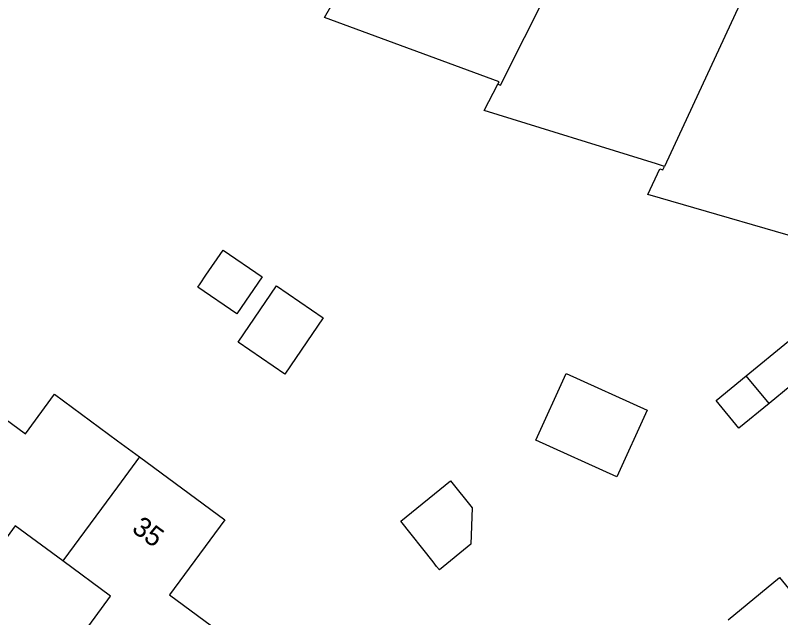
# Model space of a CAD drawing. Extents: x 163268 to 164360, y 381529 to 382285.
# Drawn here: x 163994.82 to 164033.56, y 382025.7 to 382056.18 of the extents above; entities that cross this region are included whole.
import ezdxf

# ---------------------------------------------------------------- set-up
doc = ezdxf.new("R2010")
doc.units = 0
doc.layers.add('IMGEO_Pand', color=7, linetype='Continuous')
doc.layers.add('IMGEO_Pand_nummerreeks', color=7, linetype='Continuous')

msp = doc.modelspace()

# ---------------------------------------------------------------- linework, layer by layer
at = {"layer": 'IMGEO_Pand'}
for points in [[(164019.237, 382052.689), (164019.38, 382052.637), (164024.227, 382062.276)], [(164032.042, 382058.22), (164033.103, 382060.347), (164033.389, 382060.206), (164033.142, 382059.704), (164036.288, 382058.228), (164035.748, 382057.131), (164037.56, 382056.281), (164037.279, 382055.681), (164040.358, 382054.205), (164037.138, 382047.488), (164037.634, 382047.251), (164036.26, 382044.384), (164026.833, 382047.109), (164027.447, 382048.409), (164027.599, 382048.361), (164027.68, 382048.535)], [(164032.042, 382058.22), (164032.141, 382058.171), (164027.68, 382048.535)], [(164019.237, 382052.689), (164019.304, 382052.818), (164010.469, 382056.066), (164011.179, 382057.32), (164011.327, 382057.26), (164011.412, 382057.412)], [(164027.68, 382048.535), (164027.274, 382048.661), (164018.547, 382051.364), (164019.237, 382052.689)], [(164004.471, 382043.025), (164005.337, 382044.296), (164007.31, 382042.951), (164006.036, 382041.081), (164004.063, 382042.426), (164004.177, 382042.593), (164004.471, 382043.025)], [(164008.035, 382042.486), (164010.408, 382040.869), (164008.468, 382038.023), (164006.095, 382039.641), (164008.035, 382042.486)], [(164031.818, 382037.945), (164033.955, 382039.693), (164035.106, 382038.291), (164032.969, 382036.543)], [(164022.707, 382038.065), (164026.798, 382036.201), (164025.26, 382032.824), (164021.168, 382034.688), (164022.707, 382038.065)], [(164032.969, 382036.543), (164031.442, 382035.295), (164030.291, 382036.696), (164031.818, 382037.945)], [(164032.969, 382036.543), (164031.818, 382037.945)], [(163992.626, 382036.994), (163995.332, 382035.002), (163996.808, 382037.007), (164000, 382034.657), (164001.116, 382033.835)], [(164001.116, 382033.835), (164005.432, 382030.657), (164002.633, 382026.856), (164005.459, 382024.774), (164001.872, 382019.902), (164002.588, 382019.374), (164000, 382015.859), (163999.766, 382015.541), (163995.318, 382019.588), (163995.573, 382019.862), (163995.778, 382019.672), (163996.443, 382020.583), (163995.577, 382021.23), (163999.646, 382026.797), (163997.227, 382028.572)], [(164001.116, 382033.835), (164000, 382032.325), (163997.227, 382028.572)], [(164016.85, 382032.63), (164017.942, 382031.258), (164017.875, 382029.42), (164016.284, 382028.124), (164016.146, 382028.298), (164015.965, 382028.526), (164014.33, 382030.579), (164016.85, 382032.63)], [(163997.227, 382028.572), (163994.809, 382030.347), (163992.027, 382026.558), (163991.164, 382027.191), (163990.134, 382025.788), (163990.375, 382025.61), (163990.179, 382025.343), (163986.522, 382028.69), (163987.436, 382029.933)], [(164030.903, 382025.602), (164033.505, 382027.733), (164034.629, 382026.36), (164038.757, 382029.736)]]:
    msp.add_lwpolyline(points, dxfattribs=at)

# ---------------------------------------------------------------- texts
at = {"layer": 'IMGEO_Pand_nummerreeks'}
msp.add_text('35', height=1, rotation=323.6347, dxfattribs=at).set_placement((164000.664, 382030.095))

doc.saveas('drawing.dxf')
